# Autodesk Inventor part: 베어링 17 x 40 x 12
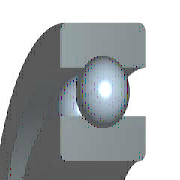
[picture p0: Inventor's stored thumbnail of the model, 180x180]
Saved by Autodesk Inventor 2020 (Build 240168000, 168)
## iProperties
IsCustomPart: 1
Created: 2012-02
Part Number: 베어링 17 x 40 x 12
Material: 강철, 연강
Description: 깊은 그루브 볼 베어링
Document SubType Name: Modeling
Standard: KS B 2023
Designer: mduedu
Standards Organization: KS
Language: ko-KR
Size Designation: 6203 - 17 x 40 x 12
Categories: <MemberInstance><Categories><Category DisplayName="샤프트 부품" InternalName="7f7aeb1f-a693-4053-b835-cee3144e0d98" Mnemonic="SHFT"><Category DisplayName="베어링" Inter
Density: 1 g/cm^3
Appearance: 노란색
Author: mduedu
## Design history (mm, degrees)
sketch "스케치" dims "d0" = 5.98 (= -0.26 x WD + 0.26 x BD)
  geometry: L1 (3.01, 14.25)-(8.99, 14.25); L2 (6, 14.25)-(6, 11.26); L3 (6, 14.25)-(6, 17.24); L4 (3.778, 12.249)-(0, 12.249); L5 (0, 8.5)-(12, 8.5); L6 (3.778, 16.251)-(0, 16.251); L7 (0, 20)-(12, 20); L8 (12, 8.5)-(12, 12.249); L9 (8.222, 12.249)-(12, 12.249); L10 (8.222, 16.251)-(12, 16.251); L11 (12, 20)-(12, 16.251); L12 (-1.4, 0)-(8.4, 0) reference; L13 (0, -0.3)-(0, 5.3) reference
  constraints: 22 end point, 4 point on line, 2 collinear, 2 perpendicular, 2 symmetric about line, 1 midpoint, 1 parallel, 14 other
  dimensions: "d9" = 17 diameter of L5 L12 (= WD); "d11" = 40 diameter of L7 L12 (= BD); "d12" = 12 distance between parallel lines of L8 L13 (= KB); "d13" = 24.498 diameter of L9 L12 (= 0.326 x BD + 0.674 x WD)
revolve "본체" stored, may be unused: angle "d6" = 90 deg
revolve "볼" stored, may be unused: angle "d7" = 90 deg
pattern_circular "IDS_ARRAYBALL[SIMPL:T]" dims angle "d3" = 360 deg
body "Solid1"
fillet "모깎기1" dims "d1" = 0.6 (= KRS)
other parameters: "WD" = 17 [user parameter; used in 5 equation terms], "BD" = 40 [user parameter; used in 5 equation terms], "KB" = 12 [user parameter; used in 1 equation term], "KRS" = 0.6 [user parameter; used in 1 equation term], "d4" = 0, "d5" = 0, "d8" = 0, "d14" = 0, "d15" = 0, "BBA" = 0 [user parameter], "BC0" = 4750000 [user parameter], "BC" = 9560000 [user parameter], "WR" = 8.5 (= 0.5 x WD) [user parameter]
